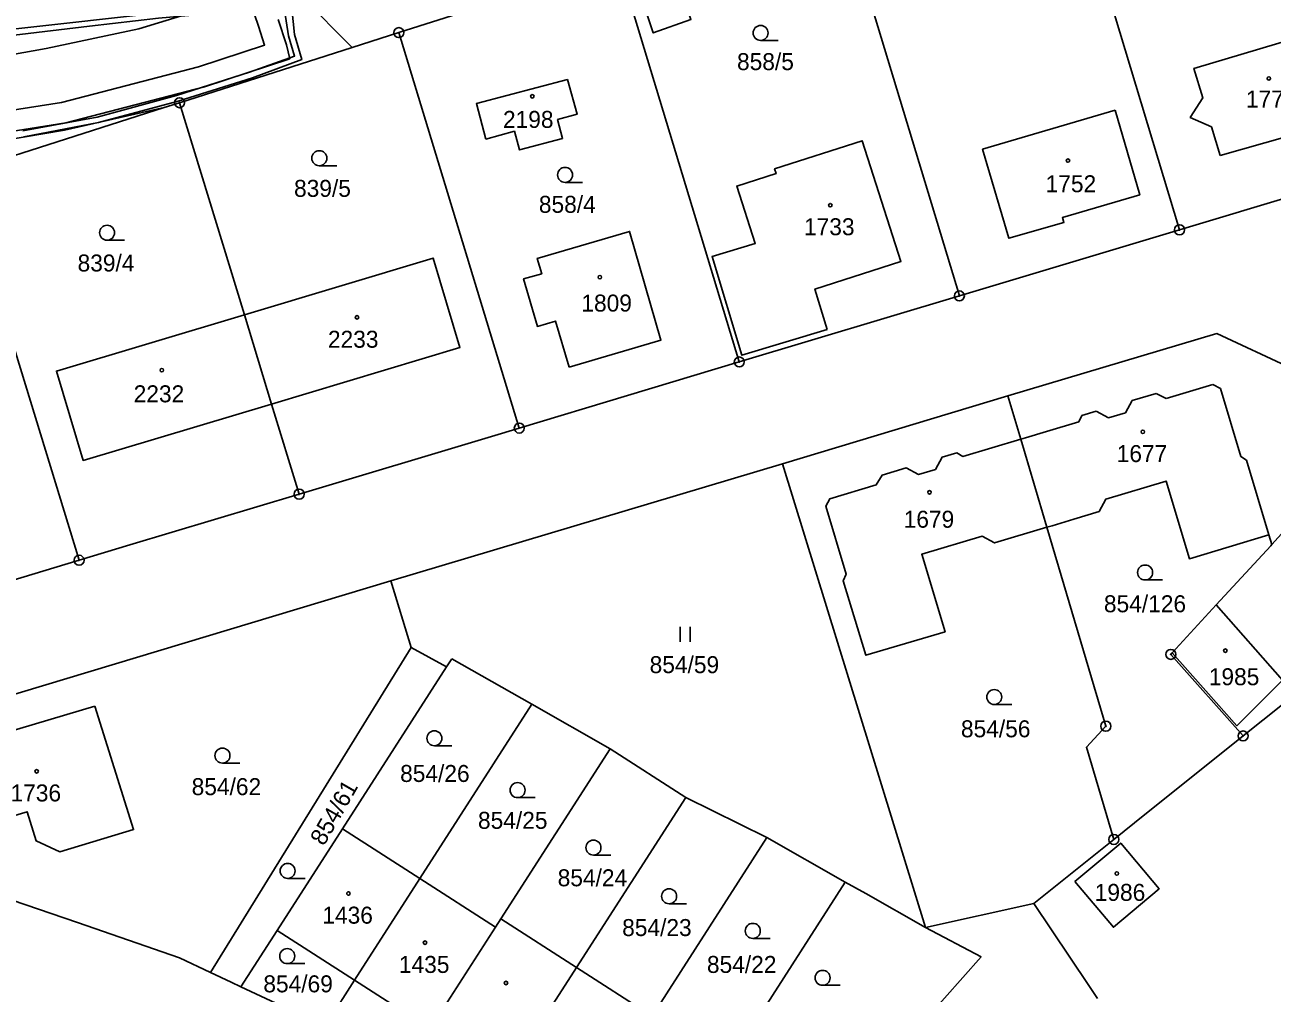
# Model space of a CAD drawing. Extents: x -680203 to -673936, y -1102717 to -1093650.
# Drawn here: x -679230.7 to -679106, y -1097616 to -1097519.2 of the extents above; entities that cross this region are included whole.
import ezdxf

# ---------------------------------------------------------------- set-up
doc = ezdxf.new("R2010")
doc.units = 0
for name, color, linetype in [('SOxx02xx_Koleje_param další_Popis10', 7, 'Continuous'), ('SOxxxxxx_Koleje_hlavní_body_Popis10', 7, 'Continuous'), ('SOxxxxxx_Koleje_LN_parametry_Popis10', 7, 'Continuous'), ('SOxxxxxx_Koleje_param další_Popis10', 7, 'Continuous'), ('SOxxxxxx_Osa_bod_P', 7, 'Continuous'), ('SOxxxxxx_Staničení_Popis10', 7, 'Continuous'), ('x_prac', 7, 'Continuous')]:
    doc.layers.add(name, color=color, linetype=linetype)

msp = doc.modelspace()

# ---------------------------------------------------------------- linework, layer by layer
at = {"layer": 'SOxx02xx_Koleje_param další_Popis10'}
for centre, radius in [((-679193.3, -1097519.93), 0.5), ((-679193.3, -1097519.93), 0.0303), ((-679215.23, -1097526.94), 0.5), ((-679215.23, -1097526.94), 0.0303), ((-679115.21, -1097539.66), 0.5), ((-679115.21, -1097539.66), 0.0303), ((-679137.23, -1097546.27), 0.5), ((-679137.23, -1097546.27), 0.0303), ((-679159.24, -1097552.88), 0.5), ((-679159.24, -1097552.88), 0.0303), ((-679181.25, -1097559.5), 0.5), ((-679181.25, -1097559.5), 0.0303), ((-679203.27, -1097566.11), 0.5), ((-679203.27, -1097566.11), 0.0303), ((-679225.28, -1097572.72), 0.5), ((-679225.28, -1097572.72), 0.0303), ((-679116.08, -1097582.14), 0.5), ((-679116.08, -1097582.14), 0.0303), ((-679122.58, -1097589.33), 0.5), ((-679122.58, -1097589.33), 0.0303), ((-679108.85, -1097590.31), 0.5), ((-679108.85, -1097590.31), 0.0303), ((-679121.78, -1097600.66), 0.5), ((-679121.78, -1097600.66), 0.0303)]:
    msp.add_circle(centre, radius, dxfattribs=at)
at = {"layer": 'SOxxxxxx_Koleje_hlavní_body_Popis10'}
for p, q in [((-679157.11, -1097520.71), (-679155.36, -1097520.71)), ((-679201.25, -1097533.24), (-679199.5, -1097533.24)), ((-679176.67, -1097534.91), (-679174.92, -1097534.91)), ((-679222.48, -1097540.7), (-679220.73, -1097540.7)), ((-679118.65, -1097574.7), (-679116.9, -1097574.7)), ((-679165.15, -1097580.9), (-679165.15, -1097579.4)), ((-679164.15, -1097580.9), (-679164.15, -1097579.4)), ((-679133.74, -1097587.16), (-679131.99, -1097587.16)), ((-679189.74, -1097591.29), (-679187.99, -1097591.29)), ((-679210.94, -1097593.02), (-679209.19, -1097593.02)), ((-679181.42, -1097596.48), (-679179.67, -1097596.48)), ((-679173.83, -1097602.23), (-679172.08, -1097602.23)), ((-679204.42, -1097604.56), (-679202.67, -1097604.56)), ((-679166.26, -1097607.1), (-679164.51, -1097607.1)), ((-679157.89, -1097610.56), (-679156.14, -1097610.56)), ((-679204.46, -1097613.09), (-679202.71, -1097613.09)), ((-679150.91, -1097615.26), (-679149.16, -1097615.26))]:
    msp.add_line(p, q, dxfattribs=at)
for centre in [(-679157.11, -1097519.96), (-679201.25, -1097532.49), (-679176.67, -1097534.16), (-679222.48, -1097539.95), (-679118.65, -1097573.95), (-679133.74, -1097586.41), (-679189.74, -1097590.54), (-679210.94, -1097592.27), (-679181.42, -1097595.73), (-679173.83, -1097601.48), (-679204.42, -1097603.81), (-679166.26, -1097606.35), (-679157.89, -1097609.81), (-679204.46, -1097612.34), (-679150.91, -1097614.51)]:
    msp.add_circle(centre, 0.75, dxfattribs=at)
at = {"layer": 'SOxxxxxx_Koleje_LN_parametry_Popis10'}
msp.add_lwpolyline([(-679262.37, -1097522.6), (-679263.09, -1097522.65), (-679262.92, -1097523.73), (-679251.15, -1097522.37), (-679237.95, -1097520.91), (-679224.23, -1097519.27), (-679217.34, -1097518.47), (-679210.55, -1097517.89), (-679208.78, -1097517.02), (-679210.98, -1097517.26), (-679255.56, -1097522.22)], close=True, dxfattribs=at)
for points in [[(-679204.89, -1097516.59), (-679204.32, -1097520.25), (-679203.73, -1097522.27), (-679208.24, -1097523.89), (-679215.54, -1097526.21), (-679223.48, -1097528.39), (-679230.92, -1097529.74)], [(-679230.82, -1097530.34), (-679223.35, -1097528.92), (-679215.38, -1097526.79), (-679207.94, -1097524.46), (-679203.01, -1097522.63), (-679203.73, -1097520.13), (-679204.09, -1097516.5)], [(-679208.13, -1097516.95), (-679207.35, -1097519.29), (-679206.72, -1097521.17), (-679213.33, -1097523.34), (-679227.04, -1097526.91)], [(-679239.25, -1097530.95), (-679226.62, -1097528.95), (-679212.75, -1097525.34), (-679204.21, -1097522.54), (-679204.54, -1097521.14), (-679205.37, -1097518.63)], [(-679227.04, -1097526.91), (-679239.45, -1097528.87)]]:
    msp.add_lwpolyline(points, dxfattribs=at)
at = {"layer": 'SOxxxxxx_Koleje_param další_Popis10'}
for centre in [(-679106.27, -1097524.51), (-679179.95, -1097526.3), (-679126.37, -1097532.73), (-679150.14, -1097537.2), (-679173.19, -1097544.4), (-679197.48, -1097548.42), (-679217.01, -1097553.7), (-679118.88, -1097559.87), (-679140.21, -1097565.92), (-679110.62, -1097581.77), (-679229.53, -1097593.84), (-679121.48, -1097604.07), (-679198.34, -1097606.07), (-679190.68, -1097610.99), (-679182.58, -1097615.02)]:
    msp.add_circle(centre, 0.175, dxfattribs=at)
at = {"layer": 'SOxxxxxx_Staničení_Popis10'}
for p, q in [((-679116.56, -1097556.53), (-679111.86, -1097555.13)), ((-679111.86, -1097555.13), (-679111.12, -1097555.53)), ((-679111.12, -1097555.53), (-679109.09, -1097562.33)), ((-679120.6, -1097557.96), (-679119.93, -1097556.75)), ((-679119.93, -1097556.75), (-679117.54, -1097556.04)), ((-679117.54, -1097556.04), (-679116.56, -1097556.53)), ((-679125.27, -1097558.88), (-679124.97, -1097558.25)), ((-679124.97, -1097558.25), (-679123.54, -1097557.82)), ((-679123.54, -1097557.82), (-679122.32, -1097558.47)), ((-679122.32, -1097558.47), (-679120.6, -1097557.96)), ((-679128.53, -1097559.85), (-679125.27, -1097558.88)), ((-679131.09, -1097560.62), (-679130.61, -1097560.48)), ((-679130.61, -1097560.48), (-679128.53, -1097559.85)), ((-679109.09, -1097562.33), (-679108.5, -1097562.72)), ((-679108.5, -1097562.72), (-679106.27, -1097570.19))]:
    msp.add_line(p, q, dxfattribs=at)
at = {"layer": 'x_prac'}
for p, q in [((-679115.21, -1097539.66), (-679127.51, -1097498.91)), ((-679137.23, -1097546.27), (-679149.44, -1097505.91)), ((-679193.3, -1097519.93), (-679171.37, -1097512.92)), ((-679159.24, -1097552.88), (-679171.37, -1097512.92)), ((-679209.15, -1097516.42), (-679219.3, -1097519.55)), ((-679197.95, -1097521.42), (-679202.94, -1097516.37)), ((-679193.3, -1097519.93), (-679197.95, -1097521.42)), ((-679181.25, -1097559.5), (-679193.3, -1097519.93)), ((-679215.23, -1097526.94), (-679197.95, -1097521.42)), ((-679216.77, -1097527.43), (-679215.23, -1097526.94)), ((-679208.75, -1097548.17), (-679215.23, -1097526.94)), ((-679115.21, -1097539.66), (-679093.2, -1097533.05)), ((-679225.28, -1097572.72), (-679237.16, -1097533.95)), ((-679137.23, -1097546.27), (-679115.21, -1097539.66)), ((-679159.24, -1097552.88), (-679137.23, -1097546.27)), ((-679206.02, -1097557.12), (-679208.75, -1097548.17)), ((-679154.93, -1097563.08), (-679132.38, -1097556.26)), ((-679132.38, -1097556.26), (-679131.09, -1097560.62)), ((-679203.27, -1097566.11), (-679206.02, -1097557.12)), ((-679131.09, -1097560.62), (-679128.48, -1097569.43)), ((-679154.93, -1097563.08), (-679194.1, -1097574.77)), ((-679154.93, -1097563.08), (-679140.62, -1097609.48)), ((-679105.99, -1097571.15), (-679102.59, -1097567.38)), ((-679194.1, -1097574.77), (-679192.05, -1097581.47)), ((-679111.55, -1097577.18), (-679115.94, -1097581.98)), ((-679093.36, -1097577.91), (-679108.85, -1097590.31)), ((-679192.05, -1097581.47), (-679212.14, -1097613.98)), ((-679192.05, -1097581.47), (-679188.52, -1097583.38)), ((-679188.01, -1097582.59), (-679188.52, -1097583.38)), ((-679180, -1097587.14), (-679188.01, -1097582.59)), ((-679188.52, -1097583.38), (-679198.94, -1097599.6)), ((-679180, -1097587.14), (-679191.2, -1097604.58)), ((-679172.16, -1097591.59), (-679180, -1097587.14)), ((-679172.16, -1097591.59), (-679183.1, -1097608.62)), ((-679164.59, -1097596.46), (-679172.16, -1097591.59)), ((-679164.59, -1097596.46), (-679175.53, -1097613.48)), ((-679156.48, -1097600.48), (-679164.59, -1097596.46)), ((-679198.94, -1097599.6), (-679205.47, -1097609.76)), ((-679191.2, -1097604.58), (-679198.94, -1097599.6)), ((-679156.48, -1097600.48), (-679167.96, -1097618.35)), ((-679148.64, -1097604.93), (-679156.48, -1097600.48)), ((-679121.78, -1097600.66), (-679129.77, -1097607.06)), ((-679191.2, -1097604.58), (-679197.73, -1097614.74)), ((-679183.63, -1097609.44), (-679191.2, -1097604.58)), ((-679148.64, -1097604.93), (-679160.92, -1097624.04)), ((-679129.77, -1097607.06), (-679140.62, -1097609.48)), ((-679183.1, -1097608.62), (-679183.63, -1097609.44)), ((-679175.53, -1097613.48), (-679183.1, -1097608.62)), ((-679209.09, -1097615.4), (-679205.47, -1097609.76)), ((-679205.47, -1097609.76), (-679197.73, -1097614.74)), ((-679167.96, -1097618.35), (-679175.53, -1097613.48)), ((-679209.09, -1097615.4), (-679200.68, -1097619.33)), ((-679197.73, -1097614.74), (-679200.68, -1097619.33)), ((-679197.73, -1097614.74), (-679190.16, -1097619.6))]:
    msp.add_line(p, q, dxfattribs=at)
for points in [[(-679165.13, -1097510.92), (-679163.88, -1097514.56), (-679165.31, -1097515.03), (-679164.08, -1097518.61), (-679167.85, -1097519.95), (-679170.33, -1097512.59)], [(-679219.3, -1097519.55), (-679228.58, -1097521.52), (-679237.92, -1097523.17), (-679254.86, -1097524.31), (-679258.85, -1097524.44), (-679262.83, -1097524.33), (-679266.74, -1097523.54), (-679275.07, -1097521.9), (-679283.52, -1097521.17), (-679290.5, -1097521.12), (-679297.01, -1097521.17), (-679303.52, -1097521.38), (-679310.5, -1097521.94), (-679317.46, -1097522.83), (-679334.19, -1097525.81), (-679345.02, -1097527.73), (-679345.39, -1097525.77), (-679356.24, -1097527.69), (-679358.21, -1097527.74), (-679359.76, -1097527.29), (-679361.23, -1097526.65)], [(-679111.14, -1097532.23), (-679104.45, -1097530.33), (-679104.68, -1097529.54), (-679098.09, -1097527.67), (-679100.56, -1097519.58), (-679113.77, -1097523.5), (-679112.88, -1097526.46), (-679114.14, -1097528.41), (-679112.01, -1097529.36), (-679111.14, -1097532.23)], [(-679184.6, -1097530.6), (-679185.54, -1097527.02), (-679176.43, -1097524.63), (-679175.45, -1097528.09), (-679177.41, -1097528.63), (-679176.92, -1097530.53), (-679181.22, -1097531.67), (-679181.74, -1097529.8), (-679184.6, -1097530.6)], [(-679281.23, -1097529.64), (-679275.7, -1097530.27), (-679270.22, -1097531.28), (-679264.61, -1097532.51), (-679258.87, -1097532.78), (-679254.7, -1097532.62), (-679236.8, -1097531.4), (-679226.73, -1097529.68), (-679216.77, -1097527.43)], [(-679237.16, -1097533.95), (-679225.71, -1097530.29), (-679216.77, -1097527.43)], [(-679121.65, -1097527.7), (-679134.91, -1097531.6), (-679132.29, -1097540.5), (-679126.77, -1097538.94), (-679126.92, -1097538.44), (-679119.18, -1097536.15), (-679121.65, -1097527.7)], [(-679150.45, -1097549.64), (-679151.68, -1097545.59), (-679143.08, -1097542.84), (-679146.96, -1097530.75), (-679155.72, -1097533.56), (-679155.56, -1097534.03), (-679159.49, -1097535.29), (-679157.65, -1097541.04), (-679161.97, -1097542.34), (-679158.99, -1097552.21), (-679150.45, -1097549.64)], [(-679176.27, -1097553.39), (-679177.62, -1097548.79), (-679179.44, -1097549.32), (-679180.82, -1097544.58), (-679179, -1097544.05), (-679179.45, -1097542.52), (-679170.21, -1097539.82), (-679167.08, -1097550.7), (-679176.27, -1097553.39)], [(-679208.75, -1097548.17), (-679189.85, -1097542.49), (-679187.18, -1097551.45), (-679206.02, -1097557.12)], [(-679206.02, -1097557.12), (-679224.86, -1097562.73), (-679227.55, -1097553.8), (-679208.75, -1097548.17)], [(-679132.38, -1097556.26), (-679111.48, -1097550.04), (-679104.04, -1097553.49), (-679102.5, -1097556.66)], [(-679181.25, -1097559.5), (-679170.41, -1097556.24), (-679159.24, -1097552.88)], [(-679203.27, -1097566.11), (-679184.04, -1097560.33), (-679181.25, -1097559.5)], [(-679131.09, -1097560.62), (-679136.87, -1097562.34), (-679137.47, -1097561.97), (-679138.96, -1097562.42), (-679139.62, -1097563.64), (-679141.33, -1097564.14), (-679142.54, -1097563.48), (-679144.94, -1097564.2), (-679145.55, -1097565.19), (-679150.18, -1097566.57), (-679150.58, -1097567.32), (-679148.55, -1097574.12), (-679148.86, -1097574.79), (-679146.6, -1097582.23), (-679138.66, -1097579.88), (-679140.99, -1097572.12), (-679134.95, -1097570.32), (-679133.7, -1097570.99), (-679128.48, -1097569.43)], [(-679128.48, -1097569.43), (-679127.95, -1097569.27), (-679125.79, -1097568.62), (-679123.26, -1097567.86), (-679122.58, -1097566.62), (-679116.55, -1097564.81), (-679114.22, -1097572.58), (-679106.27, -1097570.19), (-679105.99, -1097571.15)], [(-679225.28, -1097572.72), (-679220.19, -1097571.19), (-679203.27, -1097566.11)], [(-679121.78, -1097600.66), (-679124.52, -1097591.43), (-679122.58, -1097589.33), (-679128.48, -1097569.43)], [(-679105.99, -1097571.15), (-679106.09, -1097571.27), (-679111.55, -1097577.18)], [(-679247.3, -1097579.33), (-679234.44, -1097575.47), (-679225.28, -1097572.72)], [(-679255.42, -1097598.72), (-679255.22, -1097594.32), (-679251.99, -1097592.23), (-679194.1, -1097574.77)], [(-679111.55, -1097577.18), (-679104.92, -1097584.73), (-679109.47, -1097589.28), (-679115.94, -1097581.98)], [(-679115.94, -1097581.98), (-679116.08, -1097582.14), (-679108.85, -1097590.31)], [(-679223.71, -1097587.33), (-679232.78, -1097590.04), (-679232.46, -1097591.19), (-679238.13, -1097592.91), (-679236.13, -1097599.58), (-679230.48, -1097597.89), (-679229.58, -1097600.8), (-679227.21, -1097601.89), (-679219.83, -1097599.67), (-679223.71, -1097587.33)], [(-679108.85, -1097590.31), (-679119.71, -1097599), (-679121.78, -1097600.66)], [(-679255.42, -1097598.72), (-679225.43, -1097608.98), (-679215.25, -1097612.52), (-679212.14, -1097613.98)], [(-679125.67, -1097604.88), (-679121.09, -1097601.03), (-679117.25, -1097605.6), (-679121.82, -1097609.45), (-679125.67, -1097604.88)], [(-679140.62, -1097609.48), (-679146.6, -1097606.08), (-679148.64, -1097604.93)], [(-679123.4, -1097616.58), (-679124.35, -1097615.19), (-679129.77, -1097607.06)], [(-679183.63, -1097609.44), (-679189.62, -1097618.77), (-679190.16, -1097619.6)], [(-679163.78, -1097645.51), (-679162.36, -1097646.14), (-679149.92, -1097626.19), (-679147.9, -1097626.89), (-679135.05, -1097612.41), (-679140.62, -1097609.48)], [(-679212.14, -1097613.98), (-679210.07, -1097614.94), (-679209.09, -1097615.4)], [(-679175.53, -1097613.48), (-679182.05, -1097623.64), (-679184.86, -1097628)]]:
    msp.add_lwpolyline(points, dxfattribs=at)

# ---------------------------------------------------------------- texts
at = {"layer": 'SOxxxxxx_Osa_bod_P'}
for s, p in [('858/5', (-679159.47, -1097523.68)), ('1774', (-679108.56, -1097527.42)), ('2198', (-679182.88, -1097529.46)), ('839/5', (-679203.78, -1097536.36)), ('1752', (-679128.6, -1097535.9)), ('858/4', (-679179.29, -1097537.96)), ('1733', (-679152.77, -1097540.2)), ('839/4', (-679225.43, -1097543.83)), ('1809', (-679175.04, -1097547.84)), ('2233', (-679200.39, -1097551.46)), ('2232', (-679219.82, -1097556.92)), ('1677', (-679121.49, -1097562.9)), ('1679', (-679142.8, -1097569.47)), ('854/126', (-679122.77, -1097577.93)), ('854/59', (-679168.21, -1097584.02)), ('1985', (-679112.28, -1097585.23)), ('854/56', (-679137.07, -1097590.44)), ('854/26', (-679193.17, -1097594.91)), ('854/62', (-679214.02, -1097596.23)), ('1736', (-679232.14, -1097596.86)), ('854/25', (-679185.38, -1097599.6)), ('854/24', (-679177.41, -1097605.35)), ('1986', (-679123.69, -1097606.81)), ('1436', (-679200.95, -1097609.09)), ('854/23', (-679170.96, -1097610.33)), ('1435', (-679193.29, -1097614.02)), ('854/22', (-679162.48, -1097614.02)), ('854/69', (-679206.85, -1097615.96))]:
    msp.add_text(s, height=1.7, dxfattribs=at).set_placement(p)
msp.add_text('854/61', height=1.7, rotation=60, dxfattribs=at).set_placement((-679200.8, -1097601.39))

doc.saveas('drawing.dxf')
